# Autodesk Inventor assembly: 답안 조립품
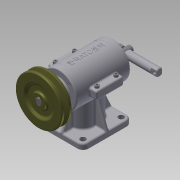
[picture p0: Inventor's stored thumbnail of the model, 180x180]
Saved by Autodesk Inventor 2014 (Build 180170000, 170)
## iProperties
Created: 2015-05
Part Number: 답안 조립품
Document SubType Name: Assembly
Designer: Administrator
Author: Administrator
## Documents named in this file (18)
- C:\Documents and Settings\Administrator\바탕 화면\350508V1030\답안 조립품.iam
- C:\Documents and Settings\Administrator\바탕 화면\350508V1030\본체.ipt
- C:\Documents and Settings\Administrator\바탕 화면\350508V1030\본체 커버.ipt
- C:\Documents and Settings\Administrator\바탕 화면\350508V1030\뒤커버.ipt
- C:\Documents and Settings\Administrator\바탕 화면\350508V1030\앞커버.ipt
- C:\Documents and Settings\Administrator\바탕 화면\350508V1030\M3x0.5x8.ipt
- C:\Documents and Settings\Administrator\바탕 화면\350508V1030\M4x0.5x14.ipt
- C:\Documents and Settings\Administrator\바탕 화면\350508V1030\편심축.ipt
- C:\Documents and Settings\Administrator\바탕 화면\350508V1030\키4x4.ipt
- C:\Documents and Settings\Administrator\바탕 화면\350508V1030\베어링 6201.ipt
- C:\Documents and Settings\Administrator\바탕 화면\350508V1030\베어링 6202.ipt
- C:\Documents and Settings\Administrator\바탕 화면\350508V1030\오일실.ipt
- C:\Documents and Settings\Administrator\바탕 화면\350508V1030\V-벨트풀리.ipt
- C:\Documents and Settings\Administrator\바탕 화면\350508V1030\멈춤나사.ipt
- C:\Documents and Settings\Administrator\바탕 화면\350508V1030\링크.ipt
- C:\Documents and Settings\Administrator\바탕 화면\350508V1030\너트 M8.ipt
- C:\Documents and Settings\Administrator\바탕 화면\350508V1030\슬라이드.ipt
- C:\Documents and Settings\Administrator\바탕 화면\350508V1030\가변 스프링.ipt
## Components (15 placed, 5 different names)
1. M4x0.5x14:1
2. M4x0.5x14:2
3. M4x0.5x14:3
4. M4x0.5x14:4
5. V-벨트풀리:1 — 플러쉬:1, 각도:2, 각도:3, 각도:6
6. KS B 1012 C - 미터 C M8:1
7. 가변 스프링:1
8. M3x0.5x8:1
9. M3x0.5x8:2
10. M3x0.5x8:3
11. M3x0.5x8:4
12. M3x0.5x8:5
13. M3x0.5x8:6
14. M3x0.5x8:7
15. M3x0.5x8:8
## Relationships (4: Angle 3, Flush 1)
- 플러쉬:1 [Flush]: V-벨트풀리:1
- 각도:2 [Angle]: V-벨트풀리:1
- 각도:3 [Angle]: V-벨트풀리:1
- 각도:6 [Angle]: V-벨트풀리:1
